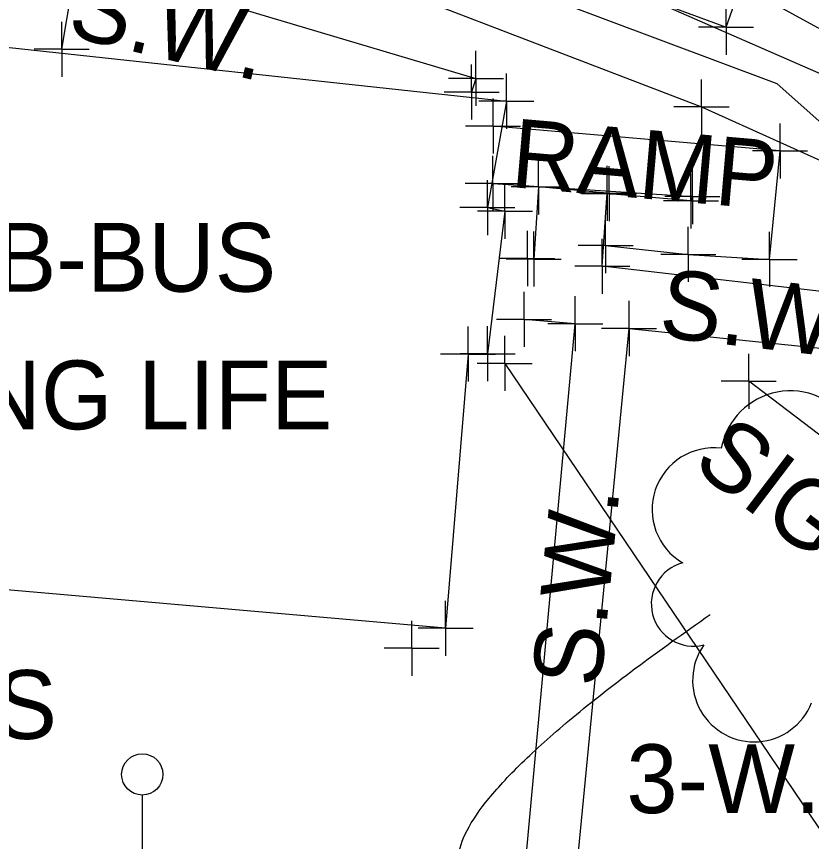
# Model space of a CAD drawing. Extents: x 0 to 1944463, y 0 to 420651.
# Drawn here: x 1942592.7 to 1942650.5, y 417779.4 to 417839.3 of the extents above; entities that cross this region are included whole.
import ezdxf

# ---------------------------------------------------------------- set-up
doc = ezdxf.new("R2010")
doc.units = 0
for name, color, linetype in [('SUR - DRG - Storm Sewer', 7, 'Continuous'), ('SUR - DTM - Breaklines', 7, 'Continuous'), ('SUR - NON-TRAN - Buildings', 7, 'Continuous'), ('SUR - NON-TRAN - Buildings - Points - Locators', 7, 'Continuous'), ('SUR - NON-TRAN - Buildings Text', 7, 'Continuous'), ('SUR - NON-TRAN - Features', 7, 'Continuous'), ('SUR - NON-TRAN - Features - Points - Locators', 7, 'Continuous'), ('SUR - NON-TRAN - Features Text', 7, 'Continuous'), ('SUR - TRAN - Features', 7, 'Continuous'), ('SUR - TRAN - Features - Points - Locators', 7, 'Continuous'), ('SUR - UTL - Electric (Lighting)', 7, 'Continuous'), ('SUR - UTL - Fiber Optic Cable (Underground)', 7, 'Continuous'), ('SUR - UTL - Overhead Wire Crossings', 7, 'Continuous'), ('SUR - UTL - Overhead Wire Crossings - Points - Locators', 7, 'Continuous'), ('SUR - UTL - Water Text', 7, 'Continuous'), ('SUR - VEG - Features', 7, 'Continuous'), ('SUR - VEG - Features Text', 7, 'Continuous')]:
    doc.layers.add(name, color=color, linetype=linetype)

msp = doc.modelspace()

# ---------------------------------------------------------------- linework, layer by layer
at = {"layer": 'SUR - DRG - Storm Sewer'}
msp.add_lwpolyline([(1942554.89, 417877.18), (1942682.23, 417821.59)], dxfattribs=at)
at = {"layer": 'SUR - DTM - Breaklines'}
msp.add_lwpolyline([(1942582.251, 417861.764), (1942583.569, 417862.955), (1942585.126, 417863.607), (1942586.766, 417863.584), (1942613.75, 417853.556), (1942645.163, 417841.696), (1942657.005, 417835.183), (1942662.276, 417830.664), (1942668.191, 417823.922)], dxfattribs=at)
at = {"layer": 'SUR - NON-TRAN - Buildings'}
msp.add_lwpolyline([(1942573.095, 417839.129), (1942628.306, 417833.158), (1942626.923, 417825.424), (1942628.201, 417825.159), (1942626.936, 417814.805), (1942625.517, 417814.781), (1942623.892, 417794.855), (1942570.341, 417799.535)], close=True, dxfattribs=at)
at = {"layer": 'SUR - NON-TRAN - Buildings - Points - Locators'}
for p, q in [((1942628.306, 417833.158), (1942628.306, 417835.158)), ((1942628.306, 417833.158), (1942626.306, 417833.158)), ((1942628.306, 417833.158), (1942630.306, 417833.158)), ((1942628.306, 417833.158), (1942628.306, 417831.158)), ((1942626.923, 417825.424), (1942626.923, 417827.424)), ((1942628.201, 417825.159), (1942628.201, 417827.159)), ((1942626.923, 417825.424), (1942624.923, 417825.424)), ((1942628.201, 417825.159), (1942626.201, 417825.159)), ((1942626.923, 417825.424), (1942628.923, 417825.424)), ((1942626.923, 417825.424), (1942626.923, 417823.424)), ((1942628.201, 417825.159), (1942630.201, 417825.159)), ((1942628.201, 417825.159), (1942628.201, 417823.159)), ((1942625.517, 417814.781), (1942625.517, 417816.781)), ((1942626.936, 417814.805), (1942626.936, 417816.805)), ((1942626.936, 417814.805), (1942624.936, 417814.805)), ((1942626.936, 417814.805), (1942628.936, 417814.805)), ((1942626.936, 417814.805), (1942626.936, 417812.805)), ((1942625.517, 417814.781), (1942623.517, 417814.781)), ((1942625.517, 417814.781), (1942627.517, 417814.781)), ((1942625.517, 417814.781), (1942625.517, 417812.781)), ((1942623.892, 417794.855), (1942623.892, 417796.855)), ((1942623.892, 417794.855), (1942621.892, 417794.855)), ((1942623.892, 417794.855), (1942625.892, 417794.855)), ((1942623.892, 417794.855), (1942623.892, 417792.855))]:
    msp.add_line(p, q, dxfattribs=at)
at = {"layer": 'SUR - NON-TRAN - Features'}
for points in [[(1942595.986, 417836.935), (1942597.15, 417843.866), (1942599.177, 417843.013), (1942601.159, 417848.033)], [(1942604.793, 417846.599), (1942603.366, 417841.587), (1942626.097, 417834.81), (1942625.782, 417833.817)], [(1942635.522, 417822.662), (1942641.524, 417822.025), (1942647.433, 417821.657), (1942648.2, 417829.541), (1942627.34, 417831.345)], [(1942627.318, 417827.178), (1942641.828, 417826.227), (1942641.719, 417825.908), (1942635.773, 417826.437)], [(1942659.3, 417818.448), (1942658.694, 417818.506), (1942658.562, 417818.491), (1942635.275, 417821.163), (1942635.633, 417826.467), (1942630.652, 417826.924), (1942630.29, 417821.685), (1942629.839, 417821.726)], [(1942606.204, 417773.773), (1942629.125, 417771.403), (1942633.314, 417816.985), (1942629.595, 417817.299)], [(1942606.017, 417770.455), (1942632.517, 417767.87), (1942637.229, 417816.642), (1942658.216, 417814.479), (1942658.327, 417814.455), (1942662.541, 417813.855)], [(1942652.708, 417807.664), (1942645.928, 417812.809)]]:
    msp.add_lwpolyline(points, dxfattribs=at)
at = {"layer": 'SUR - NON-TRAN - Features - Points - Locators'}
for p, q in [((1942595.986, 417836.935), (1942595.986, 417838.935)), ((1942595.986, 417836.935), (1942593.986, 417836.935)), ((1942595.986, 417836.935), (1942597.986, 417836.935)), ((1942595.986, 417836.935), (1942595.986, 417834.935)), ((1942626.097, 417834.81), (1942626.097, 417836.81)), ((1942625.782, 417833.817), (1942625.782, 417835.817)), ((1942626.097, 417834.81), (1942624.097, 417834.81)), ((1942626.097, 417834.81), (1942628.097, 417834.81)), ((1942626.097, 417834.81), (1942626.097, 417832.81)), ((1942625.782, 417833.817), (1942623.782, 417833.817)), ((1942625.782, 417833.817), (1942627.782, 417833.817)), ((1942625.782, 417833.817), (1942625.782, 417831.817)), ((1942627.34, 417831.345), (1942627.34, 417833.345)), ((1942627.34, 417831.345), (1942625.34, 417831.345)), ((1942627.34, 417831.345), (1942629.34, 417831.345)), ((1942627.34, 417831.345), (1942627.34, 417829.345)), ((1942648.2, 417829.541), (1942648.2, 417831.541)), ((1942648.2, 417829.541), (1942646.2, 417829.541)), ((1942648.2, 417829.541), (1942650.2, 417829.541)), ((1942648.2, 417829.541), (1942648.2, 417827.541)), ((1942627.318, 417827.178), (1942627.318, 417829.178)), ((1942630.652, 417826.924), (1942630.652, 417828.924)), ((1942635.633, 417826.467), (1942635.633, 417828.467)), ((1942635.773, 417826.437), (1942635.773, 417828.437)), ((1942641.828, 417826.227), (1942641.828, 417828.227)), ((1942641.719, 417825.908), (1942641.719, 417827.908)), ((1942627.318, 417827.178), (1942625.318, 417827.178)), ((1942627.318, 417827.178), (1942629.318, 417827.178)), ((1942627.318, 417827.178), (1942627.318, 417825.178)), ((1942630.652, 417826.924), (1942628.652, 417826.924)), ((1942630.652, 417826.924), (1942632.652, 417826.924)), ((1942630.652, 417826.924), (1942630.652, 417824.924)), ((1942635.633, 417826.467), (1942633.633, 417826.467)), ((1942635.773, 417826.437), (1942633.773, 417826.437)), ((1942635.633, 417826.467), (1942637.633, 417826.467)), ((1942635.633, 417826.467), (1942635.633, 417824.467)), ((1942635.773, 417826.437), (1942637.773, 417826.437)), ((1942635.773, 417826.437), (1942635.773, 417824.437)), ((1942641.828, 417826.227), (1942639.828, 417826.227)), ((1942641.828, 417826.227), (1942643.828, 417826.227)), ((1942641.828, 417826.227), (1942641.828, 417824.227)), ((1942641.719, 417825.908), (1942639.719, 417825.908)), ((1942641.719, 417825.908), (1942643.719, 417825.908)), ((1942641.719, 417825.908), (1942641.719, 417823.908)), ((1942635.522, 417822.662), (1942635.522, 417824.662)), ((1942641.524, 417822.025), (1942641.524, 417824.025)), ((1942629.839, 417821.726), (1942629.839, 417823.726)), ((1942630.29, 417821.685), (1942630.29, 417823.685)), ((1942647.433, 417821.657), (1942647.433, 417823.657)), ((1942635.522, 417822.662), (1942633.522, 417822.662)), ((1942635.275, 417821.163), (1942635.275, 417823.163)), ((1942635.522, 417822.662), (1942637.522, 417822.662)), ((1942635.522, 417822.662), (1942635.522, 417820.662)), ((1942641.524, 417822.025), (1942639.524, 417822.025)), ((1942641.524, 417822.025), (1942643.524, 417822.025)), ((1942641.524, 417822.025), (1942641.524, 417820.025)), ((1942629.839, 417821.726), (1942627.839, 417821.726)), ((1942630.29, 417821.685), (1942628.29, 417821.685)), ((1942629.839, 417821.726), (1942631.839, 417821.726)), ((1942629.839, 417821.726), (1942629.839, 417819.726)), ((1942630.29, 417821.685), (1942632.29, 417821.685)), ((1942630.29, 417821.685), (1942630.29, 417819.685)), ((1942647.433, 417821.657), (1942645.433, 417821.657)), ((1942647.433, 417821.657), (1942649.433, 417821.657)), ((1942647.433, 417821.657), (1942647.433, 417819.657)), ((1942635.275, 417821.163), (1942633.275, 417821.163)), ((1942635.275, 417821.163), (1942637.275, 417821.163)), ((1942635.275, 417821.163), (1942635.275, 417819.163)), ((1942629.595, 417817.299), (1942629.595, 417819.299)), ((1942633.314, 417816.985), (1942633.314, 417818.985)), ((1942637.229, 417816.642), (1942637.229, 417818.642)), ((1942629.595, 417817.299), (1942627.595, 417817.299)), ((1942629.595, 417817.299), (1942631.595, 417817.299)), ((1942629.595, 417817.299), (1942629.595, 417815.299)), ((1942633.314, 417816.985), (1942631.314, 417816.985)), ((1942633.314, 417816.985), (1942635.314, 417816.985)), ((1942633.314, 417816.985), (1942633.314, 417814.985)), ((1942637.229, 417816.642), (1942635.229, 417816.642)), ((1942637.229, 417816.642), (1942639.229, 417816.642)), ((1942637.229, 417816.642), (1942637.229, 417814.642)), ((1942645.928, 417812.809), (1942645.928, 417814.809)), ((1942645.928, 417812.809), (1942643.928, 417812.809)), ((1942645.928, 417812.809), (1942647.928, 417812.809)), ((1942645.928, 417812.809), (1942645.928, 417810.809))]:
    msp.add_line(p, q, dxfattribs=at)
at = {"layer": 'SUR - TRAN - Features'}
for points in [[(1942581.756, 417861.818), (1942603.331, 417853.714), (1942604.543, 417856.88), (1942608.142, 417855.481), (1942606.988, 417852.3), (1942644.278, 417838.532), (1942645.321, 417841.523)], [(1942580.175, 417856.641), (1942610.007, 417845.21), (1942642.489, 417832.74), (1942653.884, 417827.607), (1942663.081, 417821.558), (1942666.528, 417816.174), (1942669.105, 417810.147), (1942671.424, 417799.126), (1942671.449, 417791.645), (1942668.867, 417761.329), (1942665.888, 417734.748)]]:
    msp.add_lwpolyline(points, dxfattribs=at)
at = {"layer": 'SUR - TRAN - Features - Points - Locators'}
for p, q in [((1942644.278, 417838.532), (1942644.278, 417840.532)), ((1942644.278, 417838.532), (1942642.278, 417838.532)), ((1942644.278, 417838.532), (1942646.278, 417838.532)), ((1942644.278, 417838.532), (1942644.278, 417836.532)), ((1942642.489, 417832.74), (1942642.489, 417834.74)), ((1942642.489, 417832.74), (1942640.489, 417832.74)), ((1942642.489, 417832.74), (1942644.489, 417832.74)), ((1942642.489, 417832.74), (1942642.489, 417830.74))]:
    msp.add_line(p, q, dxfattribs=at)
at = {"layer": 'SUR - UTL - Electric (Lighting)'}
msp.add_line((1942601.841, 417782.74), (1942601.841, 417778.49), dxfattribs=at)
msp.add_circle((1942601.841, 417784.24), 1.5, dxfattribs=at)
at = {"layer": 'SUR - UTL - Fiber Optic Cable (Underground)'}
msp.add_lwpolyline([(1943675.935, 416874.811), (1943301.532, 417291.453), (1943229.017, 417377.593), (1943204.769, 417412.08), (1943079.474, 417545.559), (1943001.447, 417611.824), (1942943.851, 417666.04), (1942875.969, 417717.873), (1942785.445, 417773.544), (1942671.047, 417813.855), (1942647.996, 417834.422), (1942364.461, 417940.541)], dxfattribs=at)
at = {"layer": 'SUR - UTL - Overhead Wire Crossings'}
msp.add_lwpolyline([(1942628.183, 417814.102), (1942724.562, 417671.606)], dxfattribs=at)
at = {"layer": 'SUR - UTL - Overhead Wire Crossings - Points - Locators'}
for p, q in [((1942628.183, 417814.102), (1942628.183, 417816.102)), ((1942628.183, 417814.102), (1942626.183, 417814.102)), ((1942628.183, 417814.102), (1942630.183, 417814.102)), ((1942628.183, 417814.102), (1942628.183, 417812.102)), ((1942621.432, 417793.406), (1942621.432, 417795.406)), ((1942621.432, 417793.406), (1942619.432, 417793.406)), ((1942621.432, 417793.406), (1942623.432, 417793.406)), ((1942621.432, 417793.406), (1942621.432, 417791.406))]:
    msp.add_line(p, q, dxfattribs=at)
at = {"layer": 'SUR - VEG - Features'}
for centre, radius, start, end in [((1942648.951, 417807.002), 5.111, 31.96825, 169.49248), ((1942643.383, 417803.483), 4.486, 82.91551, 239.70443), ((1942641.919, 417796.636), 3.079, 105.03166, 283.77731), ((1942646.321, 417791.081), 4.476, 145.05235, 338.47204)]:
    msp.add_arc(centre, radius, start, end, dxfattribs=at)
at = {"layer": 'SUR - VEG - Features Text'}
msp.add_open_spline([(1942637.657, 417757.04), (1942639.066, 417772.013), (1942617.055, 417777.763), (1942643.122, 417795.861)], degree=2, dxfattribs=at)

# ---------------------------------------------------------------- texts
at = {"layer": 'SUR - NON-TRAN - Buildings Text'}
for s, p in [('2-B-BUS', (1942585.19, 417819.315)), ('LONG LIFE', (1942580.729, 417809.315))]:
    msp.add_text(s, height=5, dxfattribs=at).set_placement(p)
at = {"layer": 'SUR - NON-TRAN - Features Text'}
for s, rotation, p in [('S.W.', 346.64482, (1942596.248, 417837.935)), ('RAMP', 355.05611, (1942628.541, 417826.925)), ('S.W.', 353.45393, (1942639.295, 417816.047)), ('SIGN', 322.8047, (1942641.675, 417806.605)), ('S.W.', 84.48261, (1942635.143, 417790.5))]:
    msp.add_text(s, height=5, rotation=rotation, dxfattribs=at).set_placement(p)
at = {"layer": 'SUR - UTL - Water Text'}
msp.add_text('3-W.M.', height=5, dxfattribs=at).set_placement((1942637.033, 417781.428))
at = {"layer": 'SUR - VEG - Features Text'}
msp.add_text('GRASS', height=5, dxfattribs=at).set_placement((1942572.228, 417786.816))

doc.saveas('drawing.dxf')
